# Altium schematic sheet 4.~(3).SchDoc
size 612 x 444 mm
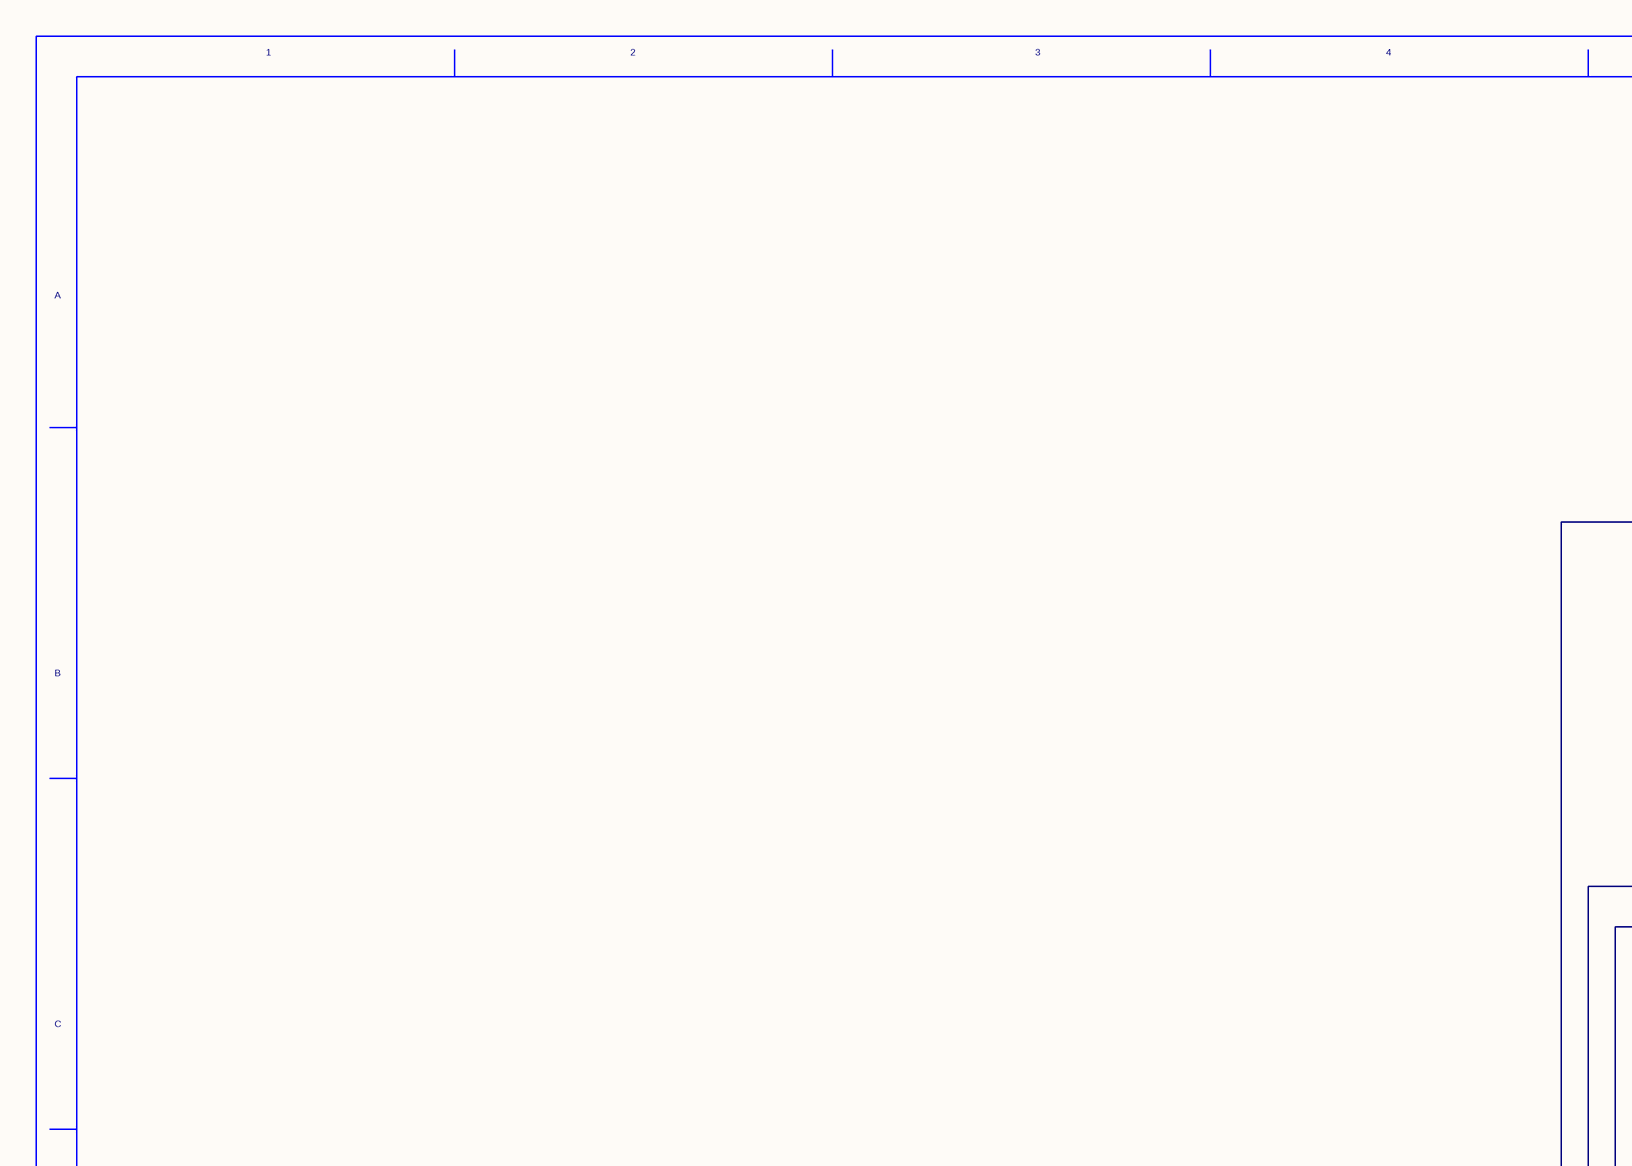
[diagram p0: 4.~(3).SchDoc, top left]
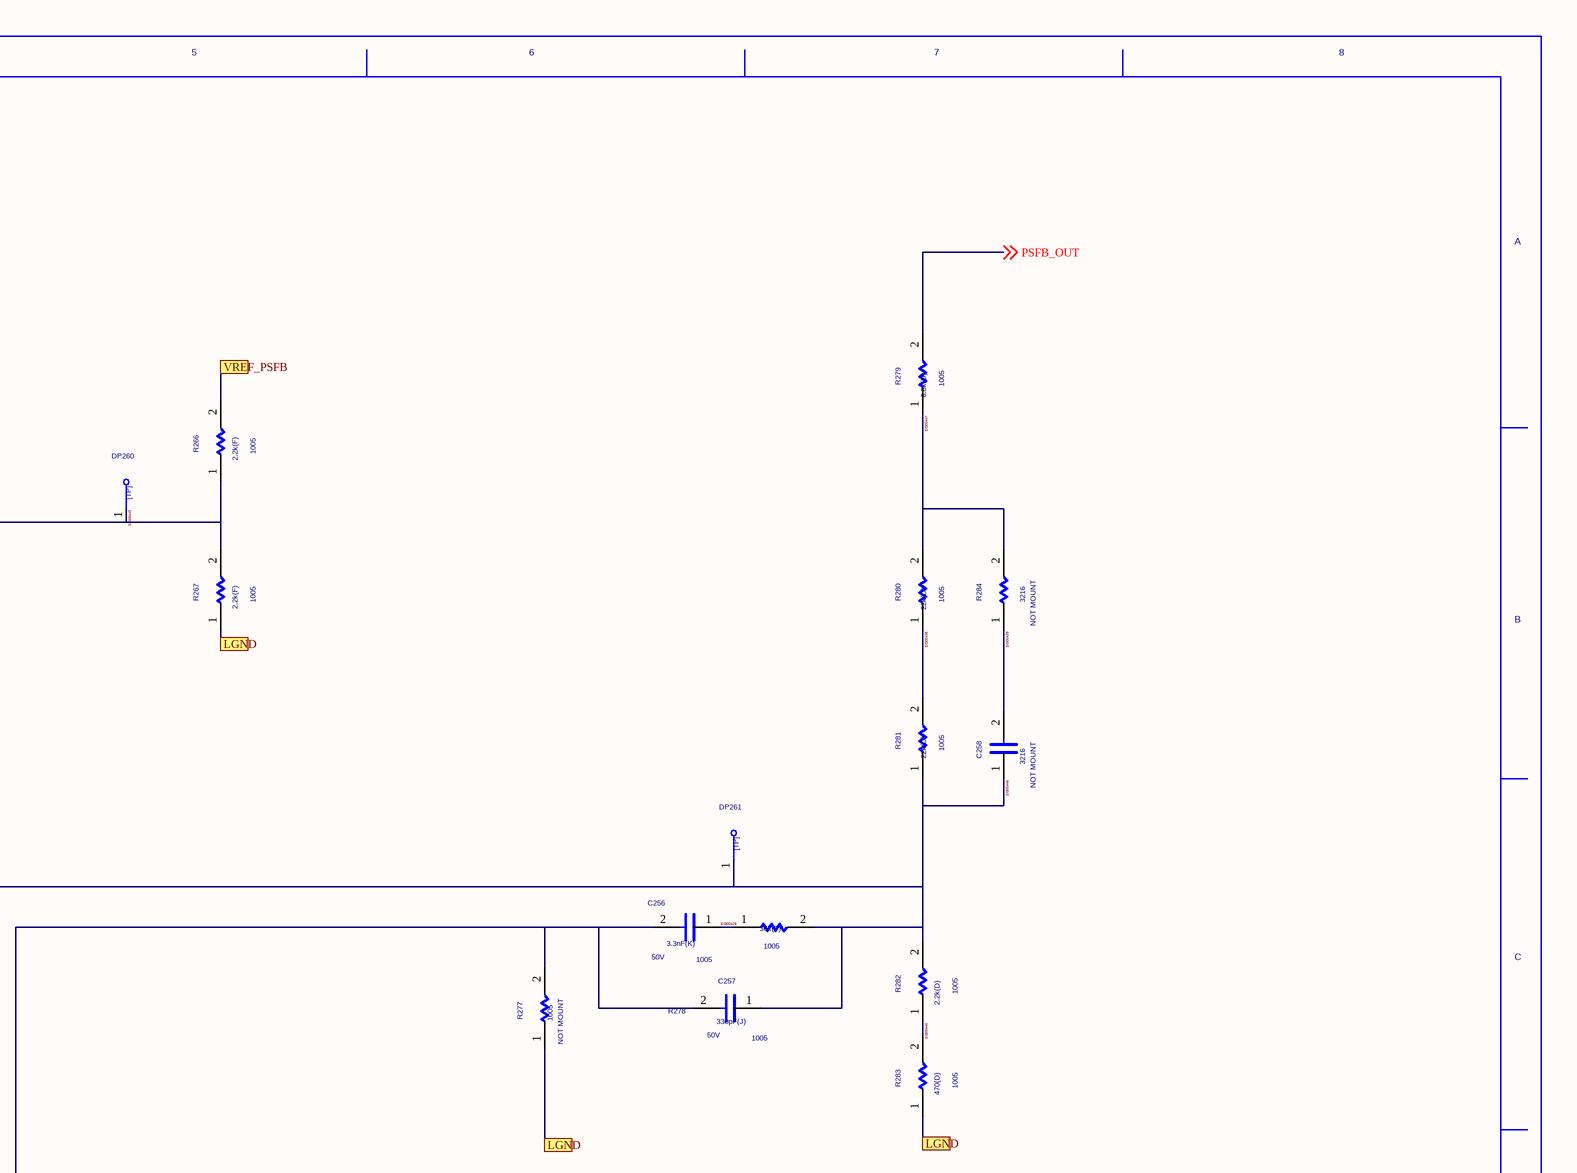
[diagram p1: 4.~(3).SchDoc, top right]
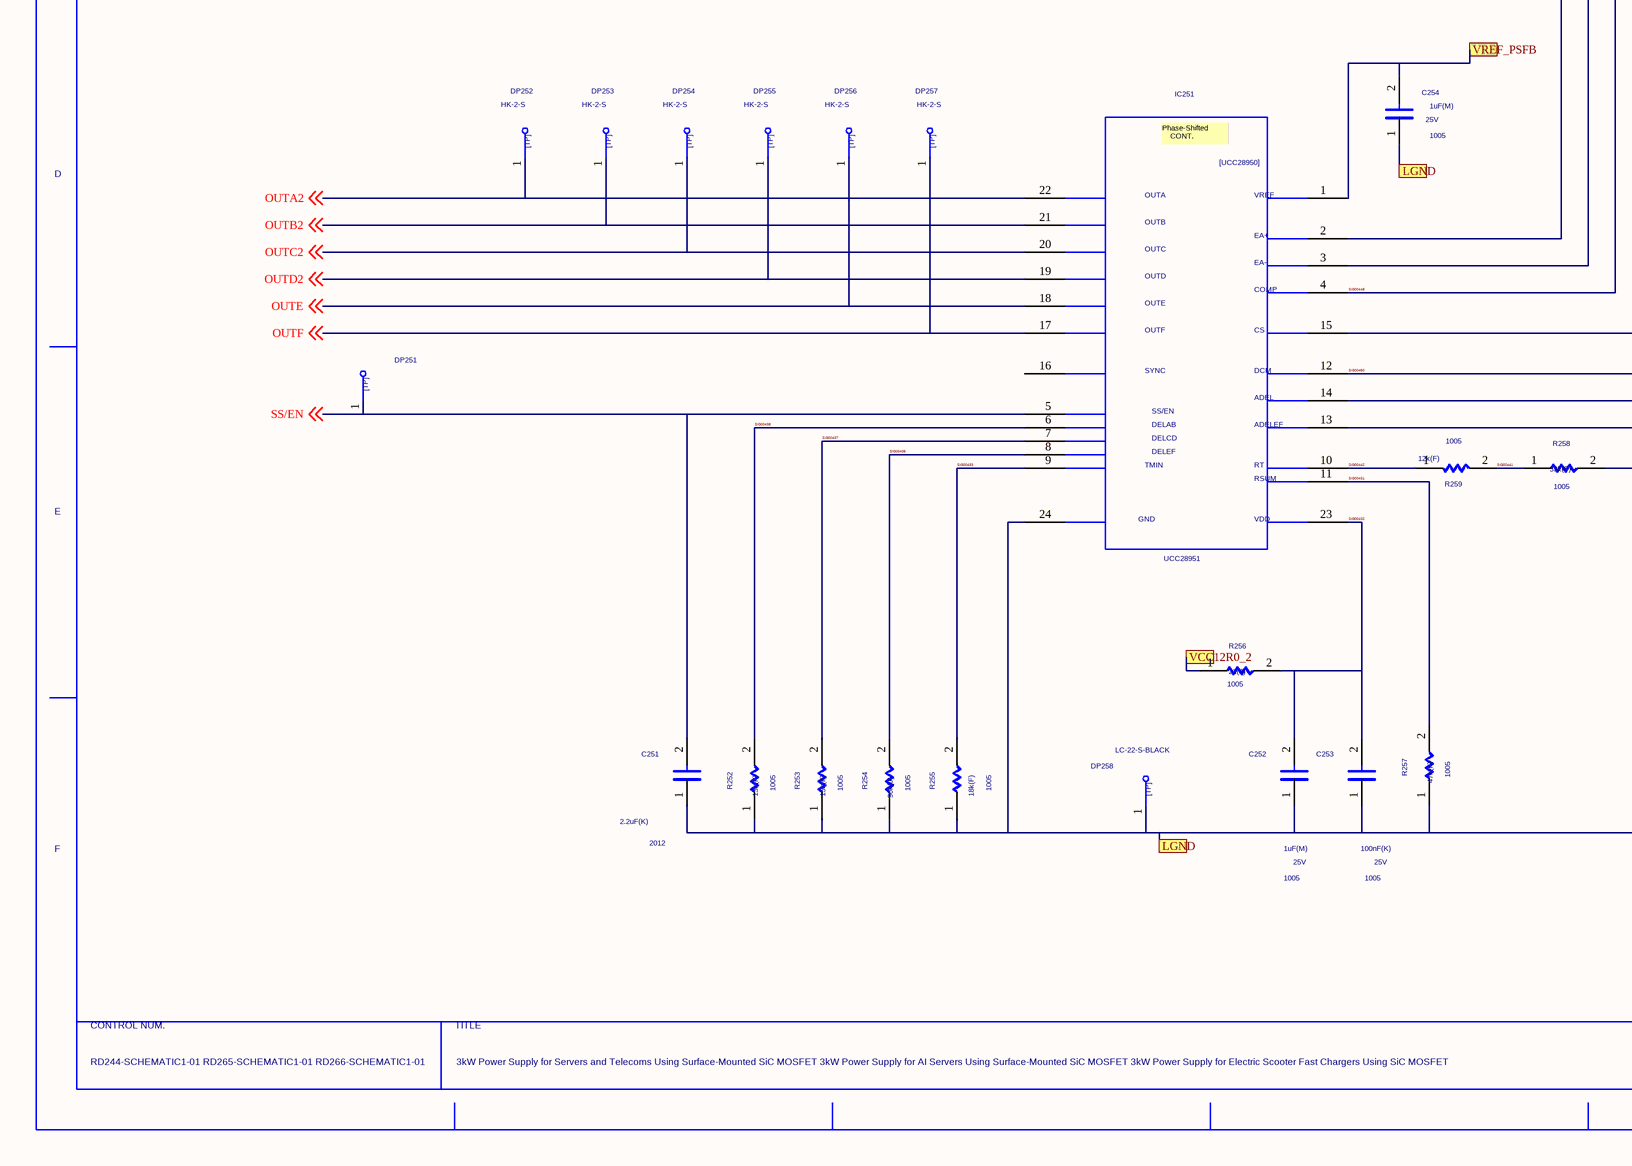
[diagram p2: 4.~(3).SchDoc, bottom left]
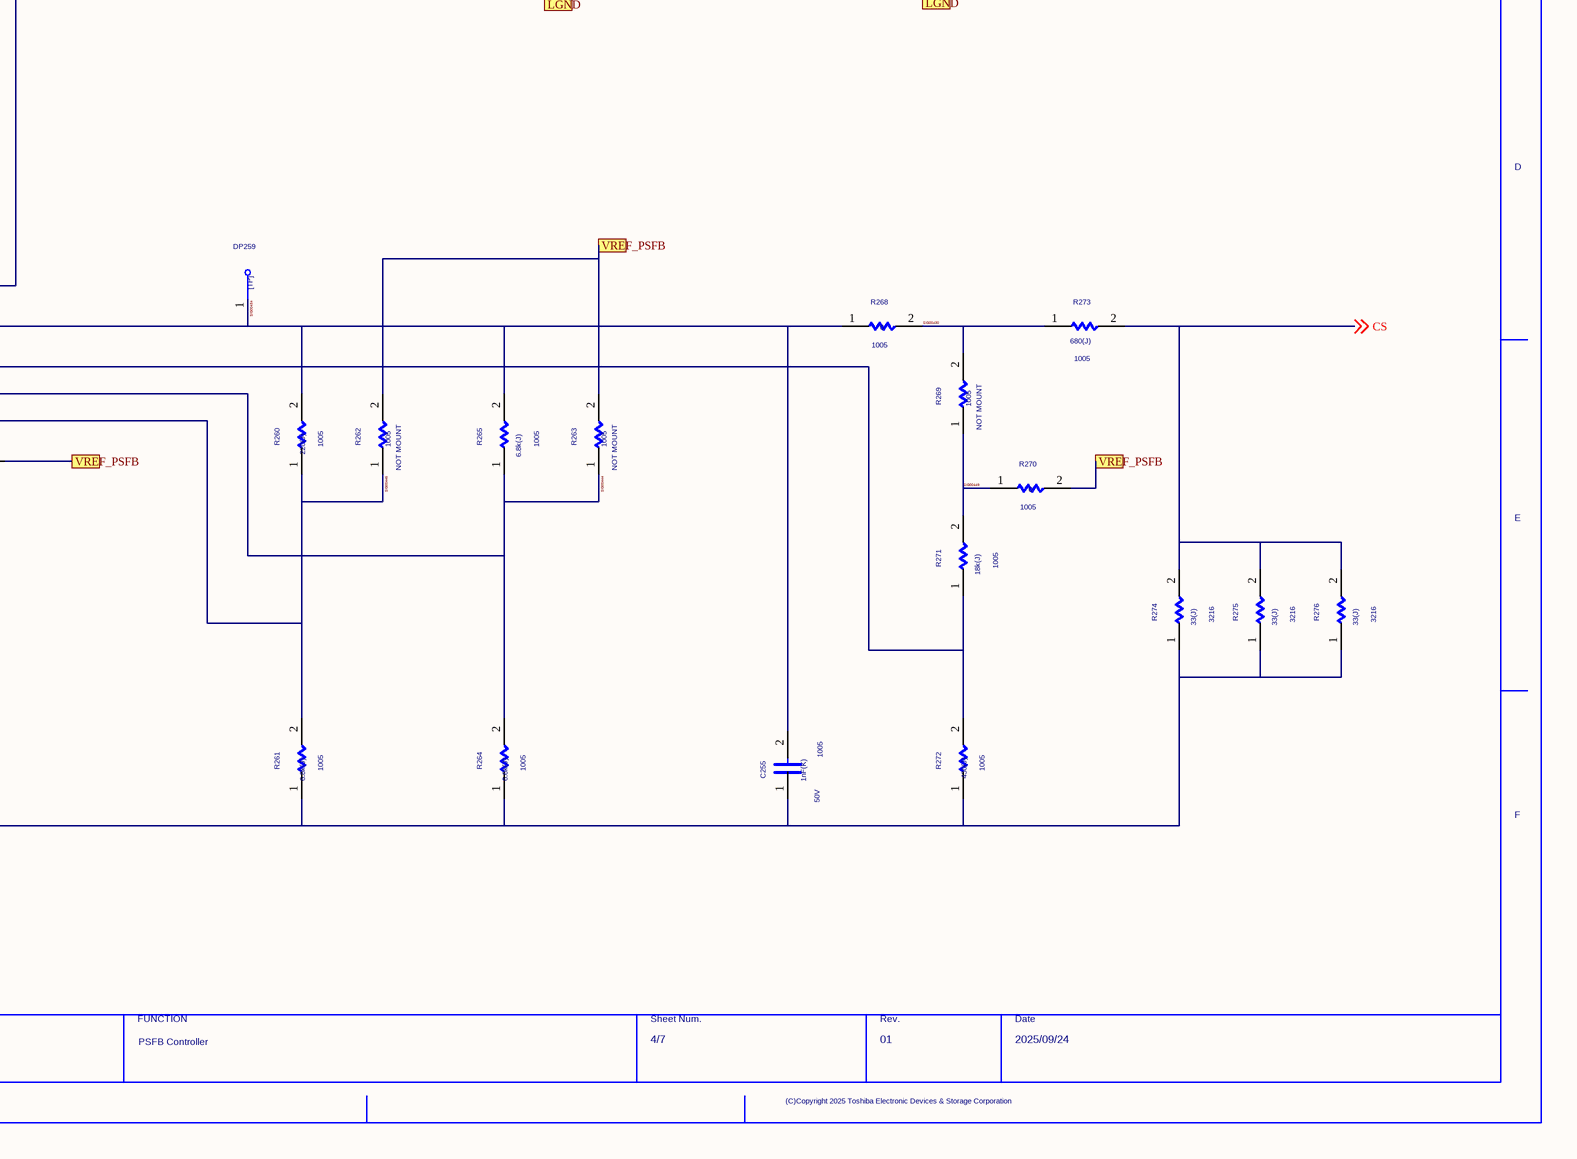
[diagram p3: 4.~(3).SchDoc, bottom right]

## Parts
C251  VAL1: 2.2uF(K)  SIZECODESMD: 2012  (hidden comment: GRM21BC71E106KE01)
C252  VAL1: 1uF(M)  VAL2: 25V  SIZECODESMD: 1005  (hidden comment: C)
C253  VAL1: 100nF(K)  VAL2: 25V  SIZECODESMD: 1005  (hidden comment: C)
C254  VAL1: 1uF(M)  VAL2: 25V  SIZECODESMD: 1005  (hidden comment: C)
C255  VAL1: 1nF(K)  VAL2: 50V  SIZECODESMD: 1005  (hidden comment: C)
C256  VAL1: 3.3nF(K)  VAL2: 50V  SIZECODESMD: 1005  (hidden comment: C)
C257  VAL1: 330pF(J)  VAL2: 50V  SIZECODESMD: 1005  (hidden comment: C)
C258  NOTMOUNT: NOT MOUNT  SIZECODESMD: 3216  (hidden comment: C)
DP251  TP  (value not drawn)
DP252  VAL3: HK-2-S  (hidden comment: TP)
DP253  VAL3: HK-2-S  (hidden comment: TP)
DP254  VAL3: HK-2-S  (hidden comment: TP)
DP255  VAL3: HK-2-S  (hidden comment: TP)
DP256  VAL3: HK-2-S  (hidden comment: TP)
DP257  VAL3: HK-2-S  (hidden comment: TP)
DP258  VAL3: LC-22-S-BLACK  (hidden comment: TP)
DP259  TP  (value not drawn)
DP260  TP  (value not drawn)
DP261  TP  (value not drawn)
IC251  VAL3: UCC28951  (hidden comment: L28950)
R252  VAL1: 13k(F)  SIZECODESMD: 1005  (hidden comment: R)
R253  VAL1: 15k(F)  SIZECODESMD: 1005  (hidden comment: R)
R254  VAL1: 90k(J)  SIZECODESMD: 1005  (hidden comment: R)
R255  VAL1: 18k(F)  SIZECODESMD: 1005  (hidden comment: R)
R256  VAL1: 22(J)  SIZECODESMD: 1005  (hidden comment: R)
R257  VAL1: 47k(F)  SIZECODESMD: 1005  (hidden comment: R)
R258  VAL1: 33k(F)  SIZECODESMD: 1005  (hidden comment: R)
R259  VAL1: 12k(F)  SIZECODESMD: 1005  (hidden comment: R)
R260  VAL1: 220(J)  SIZECODESMD: 1005  (hidden comment: R)
R261  VAL1: 6.8k(J)  SIZECODESMD: 1005  (hidden comment: R)
R262  NOTMOUNT: NOT MOUNT  SIZECODESMD: 1005  (hidden comment: R)
R263  NOTMOUNT: NOT MOUNT  SIZECODESMD: 1005  (hidden comment: R)
R264  VAL1: 6.8k(J)  SIZECODESMD: 1005  (hidden comment: R)
R265  VAL1: 6.8k(J)  SIZECODESMD: 1005  (hidden comment: R)
R266  VAL1: 2.2k(F)  SIZECODESMD: 1005  (hidden comment: R)
R267  VAL1: 2.2k(F)  SIZECODESMD: 1005  (hidden comment: R)
R268  VAL1: 0  SIZECODESMD: 1005  (hidden comment: R)
R269  NOTMOUNT: NOT MOUNT  SIZECODESMD: 1005  (hidden comment: R)
R270  VAL1: 0  SIZECODESMD: 1005  (hidden comment: R)
R271  VAL1: 18k(J)  SIZECODESMD: 1005  (hidden comment: R)
R272  VAL1: 430(J)  SIZECODESMD: 1005  (hidden comment: R)
R273  VAL1: 680(J)  SIZECODESMD: 1005  (hidden comment: R)
R274  VAL1: 33(J)  SIZECODESMD: 3216  (hidden comment: R)
R275  VAL1: 33(J)  SIZECODESMD: 3216  (hidden comment: R)
R276  VAL1: 33(J)  SIZECODESMD: 3216  (hidden comment: R)
R277  NOTMOUNT: NOT MOUNT  SIZECODESMD: 1005  (hidden comment: R)
R278  VAL1: 36k(F)  SIZECODESMD: 1005  (hidden comment: R)
R279  VAL1: 6.8k(D)  SIZECODESMD: 1005  (hidden comment: R)
R280  VAL1: 22k(D)  SIZECODESMD: 1005  (hidden comment: R)
R281  VAL1: 22k(D)  SIZECODESMD: 1005  (hidden comment: R)
R282  VAL1: 2.2k(D)  SIZECODESMD: 1005  (hidden comment: R)
R283  VAL1: 470(D)  SIZECODESMD: 1005  (hidden comment: R)
R284  NOTMOUNT: NOT MOUNT  SIZECODESMD: 3216  (hidden comment: R)
U?  DATE: 2025/09/24  DRAWINGNUMBER: RD244-SCHEMATIC1-01 / RD265-SCHEMATIC1-01 / RD266-SCHEMATIC1-01  TITLE: 3kW Power Supply for Servers and Telecoms Using Surface-Mounted SiC MOSFET / 3kW Power Supply for AI Servers Using Surface-Mounted SiC MOSFET / 3kW Power Supply for Electric Scooter Fast Chargers Using SiC MOSFET  FUNCTION: PSFB Controller  SHEETNUMBER: 4/7  REVISION: 01  (hidden comment: WAKU_DEF_A3_1)

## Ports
LGND, VCC12R0_2, VREF_PSFB

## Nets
CS: R273.2 R274.2 R275.2 R276.2 ; off-sheet CS
LGND: C251.1 C252.1 C253.1 C254.1 C255.1 DP258.1 IC251.24 R252.1 R253.1 R254.1 R255.1 R257.1 R261.1 R264.1 R267.1 R272.1 R274.1 R275.1 R276.1 R277.1 R283.1 ; port LGND
OUTA2: DP252.1 IC251.22 ; off-sheet OUTA2
OUTB2: DP253.1 IC251.21 ; off-sheet OUTB2
OUTC2: DP254.1 IC251.20 ; off-sheet OUTC2
OUTD2: DP255.1 IC251.19 ; off-sheet OUTD2
OUTE: DP256.1 IC251.18 ; off-sheet OUTE
OUTF: DP257.1 IC251.17 ; off-sheet OUTF
PSFB_OUT: R279.2 ; off-sheet PSFB_OUT
SIG00429: C256.1 R278.1
SIG00430: R268.2 R269.2 R273.1
SIG00431: IC251.11 R257.2
SIG00432: C252.2 C253.2 IC251.23 R256.2
SIG00433: IC251.9 R255.2
SIG00434: C255.2 DP259.1 IC251.15 R260.2 R265.2 R268.1
SIG00435: R280.1 R281.2
SIG00436: IC251.8 R254.2
SIG00437: IC251.7 R253.2
SIG00438: IC251.6 R252.2
SIG00439: C258.2 R284.1
SIG00440: R282.1 R283.2
SIG00441: R258.1 R259.2
SIG00442: IC251.10 R259.1
SIG00443: DP260.1 IC251.2 R266.1 R267.2
SIG00444: IC251.14 R263.1 R264.2 R265.1
SIG00445: IC251.13 R260.1 R261.2 R262.1
SIG00446: C257.1 C258.1 DP261.1 IC251.3 R278.2 R281.1 R282.2
SIG00447: R279.1 R280.2 R284.2
SIG00448: C256.2 C257.2 IC251.4 R277.2
SIG00449: R269.1 R270.1 R271.2
SIG00450: IC251.12 R271.1 R272.2
SS/EN: C251.2 DP251.1 IC251.5 ; off-sheet SS/EN
VCC12R0_2: R256.1 ; port VCC12R0_2
VREF_PSFB: C254.2 IC251.1 R258.2 R262.2 R263.2 R266.2 R270.2 ; port VREF_PSFB

Not connected (* = marked no-connect by the designer): IC251 16

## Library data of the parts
C251 = GRM21BC71E106KE01: TIME: 10:25:11; UPDATEUSER: t4887876; UPDATETIME: 16:23:00; SAVECOUNT: 11; VAL2: 25V; MAKER: Murata; OriginalSymbolOrigin: (2540,7620); CHIPSIZE: 1005; MAXGCOUNT: 1
C252-C255 = C_Dup2: OriginalSymbolOrigin: (2540,7620); COMP: PRT_52; MAXGCOUNT: 1; SAVECOUNT: 0
C256 = C_Dup2: SQ_PART_MODEL: CON_5.6N; OriginalSymbolOrigin: (2540,7620); COMP: PRT_52; MAXGCOUNT: 1; ADSCNVFLAG: ON; ADSCOMPONENTNAME: C_1005; SAVECOUNT: 0
C257 = C_Dup2: SQ_PART_MODEL: CON_560P; OriginalSymbolOrigin: (2540,7620); COMP: PRT_52; MAXGCOUNT: 1; ADSCNVFLAG: ON; ADSCOMPONENTNAME: C_1005; SAVECOUNT: 0
C258 = C_Dup2: VAL1: 10uF(K); VAL2: 25V; OriginalSymbolOrigin: (2540,7620); COMP: PRT_46; MAXGCOUNT: 1; SAVECOUNT: 0
DP251 DP259-DP261 = TP: TIME: 16:12:21; UPDATEUSER: fukuda-y; UPDATETIME: 16:18:11; SAVECOUNT: 2; SAVEAREA0: -242,-92,12810,7836; OriginalSymbolOrigin: (0,7620); USERCOMPTEXT1: Φ1.5mm; COMP: DTP815
DP252-DP257 = TP: TIME: 16:12:21; UPDATEUSER: fukuda-y; UPDATETIME: 16:18:11; SAVECOUNT: 2; SAVEAREA0: -242,-92,12810,7836; OriginalSymbolOrigin: (0,7620); COMP: PRT_44
DP258 = TP: TIME: 16:12:21; UPDATEUSER: fukuda-y; UPDATETIME: 16:18:11; SAVECOUNT: 2; SAVEAREA0: -242,-92,12810,7836; OriginalSymbolOrigin: (0,7620); COMP: PRT_34
IC251 = L28950: SAVEAREA0: -25263,1478,86635,87004; SAVECOUNT: 35; TIME: 15:02:55; UPDATEUSER: cae; UPDATETIME: 16:32:09; OriginalSymbolOrigin: (7620,83820); COMP: PRT_16
R252-R254 R256-R259 R261 R264 R266 R267 R271-R273 R278-R283 = R_Dup2: VAL2: 63mW; OriginalSymbolOrigin: (5080,5080); COMP: GDM010004481; CHIPSIZE: 1608; MAXGCOUNT: 1; SAVECOUNT: 0
R255 = R_Dup2: SQ_PART_MODEL: RES_15K; VAL2: 63mW; OriginalSymbolOrigin: (5080,5080); COMP: GDM010004481; CHIPSIZE: 1608; MAXGCOUNT: 1; ADSCNVFLAG: ON; ADSCOMPONENTNAME: R_1608; SAVECOUNT: 0
R260 R265 = R_Dup2: VAL2: 63mW; OriginalSymbolOrigin: (5080,5080); COMP: GDM010004481; CHIPSIZE: 1608; MAXGCOUNT: 1; ADSCOMPONENTNAME: R_1005; SAVECOUNT: 0
R262 R263 = R_Dup2: VAL2: 63mW; VAL1: 6.8k(J); OriginalSymbolOrigin: (5080,5080); COMP: GDM010004481; CHIPSIZE: 1608; MAXGCOUNT: 1; ADSCOMPONENTNAME: R_1005; SAVECOUNT: 0
R268 = R_Dup2: SQ_PART_MODEL: RES_0; VAL2: 63mW; OriginalSymbolOrigin: (5080,5080); COMP: GDM010004481; CHIPSIZE: 1608; MAXGCOUNT: 1; ADSCNVFLAG: ON; ADSCOMPONENTNAME: R_1608
R269 R277 = R_Dup2: VAL2: 63mW; VAL1: 0; OriginalSymbolOrigin: (5080,5080); COMP: GDM010004481; CHIPSIZE: 1608; MAXGCOUNT: 1
R270 = R_Dup2: VAL2: 63mW; OriginalSymbolOrigin: (5080,5080); COMP: GDM010004481; CHIPSIZE: 1608; MAXGCOUNT: 1
R274-R276 = R_Dup2: VAL2: 250mW; OriginalSymbolOrigin: (5080,5080); COMP: PRT_5; MAXGCOUNT: 1; SAVECOUNT: 0
R284 = R_Dup2: VAL2: 250mW; VAL1: 36(J); OriginalSymbolOrigin: (5080,5080); COMP: PRT_5; MAXGCOUNT: 1; SAVECOUNT: 0
U? = WAKU_DEF_A3_1: PLOTTIME: HH:MM; SAVEAREA0: 96913,-567914,509243,-368858; TIME: 16:14:05; UPDATEUSER: t5459927; UPDATETIME: 13:12:48; SAVECOUNT: 3; ZONEOFFSETX: 36; ZONEOFFSETY: -24; OriginalSymbolOrigin: (12700,-12700); SHTSAVECOUNT: 142; PAGENUMBER: 4; DESIGNED: TOSHIBA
